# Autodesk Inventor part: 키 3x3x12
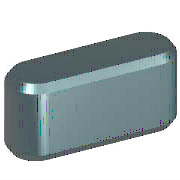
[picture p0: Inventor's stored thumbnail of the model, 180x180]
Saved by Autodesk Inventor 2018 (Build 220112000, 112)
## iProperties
Created: 2012-02
Part Number: 키 3x3x12
Material: 강철, 연강
Description: 키 및 해당 키홈
Document SubType Name: Modeling
Standard: KS B 1311
Designer: mduedu
Standards Organization: KS
Language: ko-KR
Size Designation: 3 x 3 x 12
Categories: <MemberInstance><Categories><Category DisplayName="샤프트 부품" InternalName="7f7aeb1f-a693-4053-b835-cee3144e0d98" Mnemonic="SHFT"><Category DisplayName="키" Interna
Density: 1 g/cm^3
Appearance: 노란색
IsCustomPart: 1
Author: mduedu
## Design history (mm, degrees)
workplane "Work Plane1"
workplane "Work Plane2"
sketch "스케치1"
  geometry: L1 (1.5, 1.5)-(10.5, 1.5); L2 (10.5, -1.5)-(1.5, -1.5); L3 (0, 9.4)-(0, -7.4) reference; L4 (-5, 0)-(30, 0) reference; L5 (12, 0)-(12, 7); A1 r 1.5 centre (1.5, 0) between (1.5, 1.5) and (1.5, -1.5); A2 r 1.5 centre (10.5, 0) between (10.5, -1.5) and (10.5, 1.5)
  constraints: 6 end point, 5 point on circle, 4 tangent, 3 point on line, 2 centre point, 1 horizontal, 1 parallel, 1 perpendicular
  dimensions: "d0" = 1.5 radius of A1 (= 0.5 x PB); "d13" = 1.5 radius of A2 (= 0.5 x PB); "d14" = 12 distance between parallel lines of L5 L3 (= NLG)
extrude "본체1" new body sketch "스케치1" taper "d3" = 0 deg; stored distance "d4" = 10
workplane "Work Plane3"
body "Solid1"
chamfer "모따기1" distance "d8" = 0.25 (= PHH); stored, may be unused: second distance "d9" = 0.25 (= PHH), angle "d15" = 45 deg
other parameters: "d1" = -1.8 (= -PNT), "d2" = 1.2 (= PH - PNT), "NLG" = 12 [user parameter; used in 3 equation terms], "PB" = 3 [user parameter; used in 2 equation terms], "PNT" = 1.8 [user parameter; used in 2 equation terms], "PH" = 3 [user parameter; used in 1 equation term], "PHH" = 0.25 [user parameter; used in 2 equation terms], "d10" = 0, "d16" = 0, "d17" = 0, "d18" = 0, "WDMIN" = 8 [user parameter], "PLB2" = 12 (= NLG) [user parameter], "PLB1" = 12 (= NLG) [user parameter], "RR" = 0.08 [user parameter], "PUEB" = 1.4 [user parameter]
